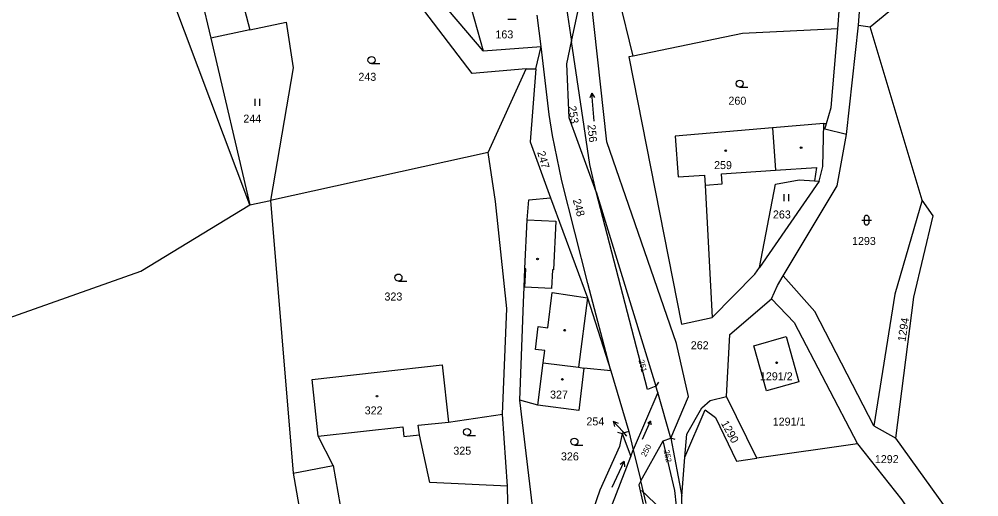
# Model space of a CAD drawing. Extents: x -520431 to -517205, y -1075927 to -1074013.
# Drawn here: x -518004.6 to -517800.7, y -1075007.9 to -1074906.6 of the extents above; entities that cross this region are included whole.
import ezdxf

# ---------------------------------------------------------------- set-up
doc = ezdxf.new("R2010")
doc.units = 0
for name, color, linetype in [('Hranice parcel', 7, 'Continuous'), ('Parcelní čísla', 7, 'Continuous'), ('Pop  PČ popisy', 7, 'Continuous'), ('Vnitřní kresba', 7, 'Continuous'), ('Značky budov', 7, 'Continuous'), ('Značky kultur', 7, 'Continuous')]:
    doc.layers.add(name, color=color, linetype=linetype)

msp = doc.modelspace()

# ---------------------------------------------------------------- linework, layer by layer
at = {"layer": 'Hranice parcel'}
for p, q in [((-517916.16, -1074877.09), (-517906.02, -1074913.26)), ((-517874.17, -1074914.39), (-517880.42, -1074888.5)), ((-517955.54, -1074945.96), (-517976.15, -1074891.26)), ((-517967.21, -1074896.33), (-517963.86, -1074910.57)), ((-517888.27, -1074904.24), (-517887.22, -1074911.33)), ((-517893.7, -1074912.38), (-517894.51, -1074905.72)), ((-517955.57, -1074908.82), (-517963.86, -1074910.57)), ((-517832.09, -1074925.31), (-517830.67, -1074908.59)), ((-517828.8, -1074931.01), (-517826.24, -1074907.87)), ((-517826.24, -1074907.87), (-517823.83, -1074908.18)), ((-517812.75, -1074944.98), (-517823.83, -1074908.18)), ((-517963.86, -1074910.57), (-517955.54, -1074945.96)), ((-517883.35, -1074937.44), (-517887.22, -1074911.33)), ((-517906.02, -1074913.26), (-517893.7, -1074912.38)), ((-517894.82, -1074917.08), (-517893.7, -1074912.38)), ((-517891.96, -1074926.82), (-517893.7, -1074912.38)), ((-517904.92, -1074934.86), (-517896.86, -1074917.08)), ((-517896.86, -1074917.08), (-517894.82, -1074917.08)), ((-517833.05, -1074928.68), (-517832.09, -1074925.31)), ((-517833.62, -1074928.7), (-517833.05, -1074928.68)), ((-517833.4, -1074929.93), (-517833.05, -1074928.68)), ((-517828.8, -1074931.01), (-517833.4, -1074929.93)), ((-517904.92, -1074934.86), (-517951.17, -1074945.05)), ((-517882.02, -1074943.22), (-517883.35, -1074937.44)), ((-517834.64, -1074940.93), (-517847.29, -1074959.23)), ((-517835.6, -1074940.84), (-517834.64, -1074940.93)), ((-517882.02, -1074943.22), (-517869.3, -1074984.41)), ((-517955.54, -1074945.96), (-517951.17, -1074945.05)), ((-517951.17, -1074945.05), (-517946.33, -1075002.93)), ((-517857.38, -1074969.84), (-517848.29, -1074960.69)), ((-517848.29, -1074960.69), (-517847.29, -1074959.23)), ((-517878.91, -1074981.15), (-517875.08, -1074994.08)), ((-517868.91, -1074985.79), (-517869.3, -1074984.41)), ((-517868.91, -1074985.79), (-517874.14, -1074997.93)), ((-517866.16, -1074995.48), (-517868.91, -1074985.79)), ((-517847.84, -1074999.74), (-517854.33, -1074986.61)), ((-517913.38, -1074992.05), (-517901.93, -1074990.4)), ((-517900.8, -1075005.69), (-517901.93, -1074990.4)), ((-517823.05, -1074992.89), (-517818.33, -1074995.49)), ((-517875.08, -1074994.08), (-517876.51, -1074994.46)), ((-517876.51, -1074994.46), (-517874.62, -1074999.39)), ((-517875.08, -1074994.08), (-517874.14, -1074997.93)), ((-517872.54, -1075004.49), (-517867.8, -1074996.01)), ((-517867.8, -1074996.01), (-517866.16, -1074995.48)), ((-517866.16, -1074995.48), (-517863.83, -1075007.75)), ((-517826.51, -1074996.69), (-517847.84, -1074999.74)), ((-517805.72, -1075013), (-517818.33, -1074995.49)), ((-517874.62, -1074999.39), (-517874.14, -1074997.93)), ((-517874.14, -1074997.93), (-517872.54, -1075004.49)), ((-517863.83, -1075007.75), (-517863.14, -1074999.53)), ((-517946.33, -1075002.93), (-517942.74, -1075023.47)), ((-517871.36, -1075009.31), (-517872.54, -1075004.49)), ((-517900.62, -1075018.12), (-517900.8, -1075005.69))]:
    msp.add_line(p, q, dxfattribs=at)
for points in [[(-517826.24, -1074907.87), (-517823.91, -1074876.47), (-517825.37, -1074854.78), (-517830.92, -1074826.23), (-517838.91, -1074803.56), (-517840.09, -1074786.1), (-517837.67, -1074775.28), (-517834.63, -1074772.92)], [(-517866.16, -1074995.48), (-517862.38, -1074986.61), (-517864.95, -1074975.4), (-517873.72, -1074950.03), (-517879.74, -1074932.6), (-517886.29, -1074872.63), (-517887.86, -1074858.24), (-517885.47, -1074844.46), (-517882.79, -1074830.19), (-517881.89, -1074814.38), (-517886.58, -1074786.88), (-517891.01, -1074778.56), (-517892.03, -1074778.59)], [(-517887.22, -1074911.33), (-517885.91, -1074904.98), (-517885.83, -1074899.23), (-517886.23, -1074894.07), (-517890.18, -1074879.3), (-517893.63, -1074862.06)], [(-517830.67, -1074908.59), (-517827.82, -1074871.24), (-517828.41, -1074867.38)], [(-517823.83, -1074908.18), (-517792.88, -1074882.75), (-517789.56, -1074873.12), (-517772.7, -1074878.11)], [(-517906.02, -1074913.26), (-517924.38, -1074891.66), (-517935.96, -1074876.96)], [(-517896.86, -1074917.08), (-517908.36, -1074918.13), (-517932.74, -1074886.06), (-517931.32, -1074891.93), (-517934.39, -1074892.34), (-517935.66, -1074887.24), (-517944.38, -1074892.59), (-517958.59, -1074897.16), (-517955.57, -1074908.82)], [(-517955.57, -1074908.82), (-517947.88, -1074907.19), (-517946.36, -1074916.9), (-517951.17, -1074945.05)], [(-517830.67, -1074908.59), (-517850.88, -1074909.62), (-517874.17, -1074914.39)], [(-517882.02, -1074943.22), (-517887.7, -1074927.48), (-517888.2, -1074916.03), (-517887.22, -1074911.33)], [(-517874.17, -1074914.39), (-517875.05, -1074914.56), (-517863.85, -1074971.3), (-517857.38, -1074969.84)], [(-517894.82, -1074917.08), (-517895.99, -1074932.61), (-517891.72, -1074944.49)], [(-517878.91, -1074981.15), (-517883.77, -1074962.62), (-517889.26, -1074940.9), (-517891.27, -1074931.27), (-517891.96, -1074926.82)], [(-517833.62, -1074928.7), (-517844.54, -1074929.63), (-517865.19, -1074931.36), (-517864.56, -1074940.04), (-517858.96, -1074939.64), (-517858.82, -1074941.81), (-517857.38, -1074969.84)], [(-517834.64, -1074940.93), (-517833.84, -1074937.84), (-517833.62, -1074928.7)], [(-517842.26, -1074961.05), (-517830.81, -1074941.95), (-517828.8, -1074931.01)], [(-517901.93, -1074990.4), (-517900.97, -1074967.93), (-517903.38, -1074945.24), (-517904.92, -1074934.86)], [(-517847.29, -1074959.23), (-517843.89, -1074941.61), (-517838.88, -1074940.68), (-517835.6, -1074940.84)], [(-517869.3, -1074984.41), (-517871.1, -1074985.17), (-517882.02, -1074943.22)], [(-518091.7, -1074993.89), (-518020.99, -1074971.84), (-518008.1, -1074970.4), (-517978.75, -1074960.03), (-517955.54, -1074945.96)], [(-517898.22, -1074987.43), (-517897.41, -1074966.66), (-517897.28, -1074963.41), (-517897.18, -1074959.5), (-517896.64, -1074949.13), (-517896.32, -1074944.9), (-517891.72, -1074944.49)], [(-517891.72, -1074944.49), (-517883.84, -1074965.68), (-517878.91, -1074981.15)], [(-517812.75, -1074944.98), (-517818.56, -1074964.92), (-517823.05, -1074992.89)], [(-517818.33, -1074995.49), (-517814.52, -1074965.57), (-517810.43, -1074948.3), (-517812.75, -1074944.98)], [(-517844.79, -1074965.88), (-517843.5, -1074963.11), (-517842.26, -1074961.05)], [(-517823.05, -1074992.89), (-517835.52, -1074968.59), (-517842.26, -1074961.05)], [(-517854.33, -1074986.61), (-517853.6, -1074973.47), (-517844.79, -1074965.88)], [(-517844.79, -1074965.88), (-517839.92, -1074970.95), (-517826.51, -1074996.69)], [(-517845.85, -1074985.43), (-517848.52, -1074975.88), (-517841.64, -1074973.93), (-517838.96, -1074983.51), (-517845.85, -1074985.43)], [(-517946.33, -1075002.93), (-517937.86, -1075001.24), (-517941.02, -1074995.02), (-517942.34, -1074983.03), (-517914.72, -1074979.9), (-517913.38, -1074992.05)], [(-517878.91, -1074981.15), (-517884.59, -1074980.59), (-517885.69, -1074989.6), (-517894.42, -1074988.45), (-517898.22, -1074987.43)], [(-517863.14, -1074999.53), (-517862.72, -1074994.61), (-517859.53, -1074989.04), (-517857.75, -1074987.49), (-517854.33, -1074986.61)], [(-517883.95, -1075014.53), (-517891.87, -1075012.84), (-517894.26, -1075011.97), (-517895.52, -1075009.88), (-517898.22, -1074987.43)], [(-517863.14, -1074999.53), (-517858.84, -1074989.45), (-517856.68, -1074991.12), (-517852.18, -1075000.36), (-517847.84, -1074999.74)], [(-517919.55, -1074994.75), (-517919.81, -1074992.74), (-517913.38, -1074992.05)], [(-517900.8, -1075005.69), (-517917.3, -1075004.87), (-517919.55, -1074994.75)], [(-517876.51, -1074994.46), (-517877.07, -1074997.27), (-517881.21, -1075006.5), (-517883.95, -1075014.53)], [(-517860.18, -1075049.08), (-517863.89, -1075019.56), (-517865.26, -1075006.59), (-517867.8, -1074996.01)], [(-517826.51, -1074996.69), (-517817.05, -1075008.56), (-517812.83, -1075014.89)], [(-517883.95, -1075014.53), (-517880.72, -1075015.09), (-517874.62, -1074999.39)], [(-517872.54, -1075004.49), (-517872.93, -1075005.38), (-517872.02, -1075009.48)], [(-517862.16, -1075027.2), (-517863.63, -1075014.15), (-517863.83, -1075007.75)]]:
    msp.add_lwpolyline(points, dxfattribs=at)
at = {"layer": 'Pop  PČ popisy'}
for p, q in [((-517876.36, -1074994.09), (-517878.41, -1074991.9)), ((-517878.41, -1074991.9), (-517877.36, -1074992.29)), ((-517878.41, -1074991.9), (-517878.09, -1074992.97)), ((-517875.47, -1074995.04), (-517876.36, -1074994.09)), ((-517872.34, -1075006.58), (-517871.32, -1075007.56)), ((-517871.32, -1075007.56), (-517869.16, -1075009.65))]:
    msp.add_line(p, q, dxfattribs=at)
at = {"layer": 'Vnitřní kresba'}
for p, q in [((-517844.54, -1074929.63), (-517843.93, -1074938.62)), ((-517843.93, -1074938.62), (-517835.19, -1074938.02)), ((-517835.19, -1074938.02), (-517835.6, -1074940.84)), ((-517855.4, -1074939.42), (-517843.93, -1074938.62)), ((-517855.24, -1074941.54), (-517855.4, -1074939.42)), ((-517858.82, -1074941.81), (-517855.24, -1074941.54)), ((-517896.64, -1074949.13), (-517890.57, -1074949.43)), ((-517890.57, -1074949.43), (-517891.06, -1074959.78)), ((-517896.96, -1074959.51), (-517897.18, -1074959.5)), ((-517897.12, -1074963.42), (-517896.96, -1074959.51)), ((-517891.28, -1074959.77), (-517891.51, -1074963.69)), ((-517891.06, -1074959.78), (-517891.28, -1074959.77)), ((-517891.51, -1074963.69), (-517897.12, -1074963.42)), ((-517892.3, -1074972.06), (-517891.33, -1074964.56)), ((-517891.33, -1074964.56), (-517883.84, -1074965.68)), ((-517883.84, -1074965.68), (-517885.77, -1074980.44)), ((-517894.9, -1074976.63), (-517894.3, -1074971.8)), ((-517894.3, -1074971.8), (-517892.3, -1074972.06)), ((-517892.92, -1074976.89), (-517894.9, -1074976.63)), ((-517893.26, -1074979.49), (-517892.92, -1074976.89)), ((-517894.42, -1074988.45), (-517893.26, -1074979.49)), ((-517893.26, -1074979.49), (-517885.77, -1074980.44)), ((-517885.77, -1074980.44), (-517884.59, -1074980.59)), ((-517868.73, -1074983.59), (-517869.3, -1074984.41)), ((-517941.02, -1074995.02), (-517923.08, -1074993.09)), ((-517923.08, -1074993.09), (-517922.82, -1074995.15)), ((-517922.82, -1074995.15), (-517919.55, -1074994.75)), ((-517877.48, -1074994.2), (-517876.51, -1074994.46)), ((-517865.2, -1074995.77), (-517866.16, -1074995.48)), ((-517937.86, -1075001.24), (-517933.34, -1075027.34))]:
    msp.add_line(p, q, dxfattribs=at)
at = {"layer": 'Značky budov'}
for centre in [(-517838.47, -1074933.84), (-517854.49, -1074934.48), (-517894.45, -1074957.45), (-517888.68, -1074972.57), (-517843.67, -1074979.48), (-517889.18, -1074983), (-517928.54, -1074986.56)]:
    msp.add_circle(centre, 0.175, dxfattribs=at)
at = {"layer": 'Značky kultur'}
for p, q in [((-517900.77, -1074906.58), (-517899.02, -1074906.58)), ((-517929.72, -1074916), (-517927.97, -1074916)), ((-517851.53, -1074921), (-517849.78, -1074921)), ((-517954.41, -1074924.96), (-517954.41, -1074923.46)), ((-517953.41, -1074924.96), (-517953.41, -1074923.46)), ((-517882.91, -1074922.26), (-517883.33, -1074923.28)), ((-517882.39, -1074928.24), (-517882.91, -1074922.26)), ((-517882.91, -1074922.26), (-517882.33, -1074923.19)), ((-517842.07, -1074945.18), (-517842.07, -1074943.68)), ((-517841.07, -1074945.18), (-517841.07, -1074943.68)), ((-517825.54, -1074949.22), (-517823.54, -1074949.22)), ((-517825.04, -1074948.72), (-517825.04, -1074949.72)), ((-517824.04, -1074949.72), (-517824.04, -1074948.72)), ((-517924, -1074962.15), (-517922.25, -1074962.15)), ((-517872.15, -1074995.69), (-517870.45, -1074991.85)), ((-517870.45, -1074991.85), (-517871.04, -1074992.33)), ((-517870.45, -1074991.85), (-517870.4, -1074992.62)), ((-517909.41, -1074994.91), (-517907.66, -1074994.91)), ((-517886.61, -1074996.95), (-517884.86, -1074996.95)), ((-517878.58, -1075005.86), (-517876.05, -1075000.42)), ((-517876.05, -1075000.42), (-517876.92, -1075001.09)), ((-517876.05, -1075000.42), (-517876.01, -1075001.52))]:
    msp.add_line(p, q, dxfattribs=at)
for centre in [(-517929.72, -1074915.25), (-517851.53, -1074920.25), (-517924, -1074961.4), (-517909.41, -1074994.16), (-517886.61, -1074996.2)]:
    msp.add_circle(centre, 0.75, dxfattribs=at)
for centre, start, end in [((-517824.54, -1074948.72), 0, 180), ((-517824.54, -1074949.72), 180, 359.9879)]:
    msp.add_arc(centre, 0.5, start, end, dxfattribs=at)

# ---------------------------------------------------------------- texts
at = {"layer": 'Parcelní čísla'}
for s, p in [('163', (-517903.4, -1074910.65)), ('243', (-517932.51, -1074919.65)), ('260', (-517853.9, -1074924.72)), ('244', (-517956.95, -1074928.53)), ('259', (-517856.95, -1074938.38)), ('263', (-517844.45, -1074948.86)), ('1293', (-517827.65, -1074954.48)), ('323', (-517926.97, -1074966.27)), ('262', (-517861.9, -1074976.61)), ('1291/2', (-517847.21, -1074983.19)), ('327', (-517891.79, -1074987.07)), ('322', (-517931.17, -1074990.43)), ('254', (-517884.07, -1074992.76)), ('1291/1', (-517844.5, -1074992.81)), ('325', (-517912.34, -1074998.98)), ('326', (-517889.48, -1075000.19)), ('1292', (-517822.8, -1075000.77))]:
    msp.add_text(s, height=1.7, dxfattribs=at).set_placement(p)
for s, height, rotation, p in [('253', 1.7, 279, (-517887.95, -1074925.09)), ('256', 1.7, 276, (-517883.86, -1074929)), ('247', 1.7, 286, (-517894.54, -1074934.81)), ('248', 1.7, 285, (-517886.98, -1074944.94)), ('1294', 1.7, 81, (-517816.31, -1074975.07)), ('251', 1.2, 285, (-517873.03, -1074978.99)), ('1290', 1.7, 299, (-517855.55, -1074992.3)), ('250', 1.2, 62, (-517871.48, -1074999.54)), ('252', 1.2, 282, (-517867.67, -1074998.07))]:
    msp.add_text(s, height=height, rotation=rotation, dxfattribs=at).set_placement(p)

doc.saveas('drawing.dxf')
